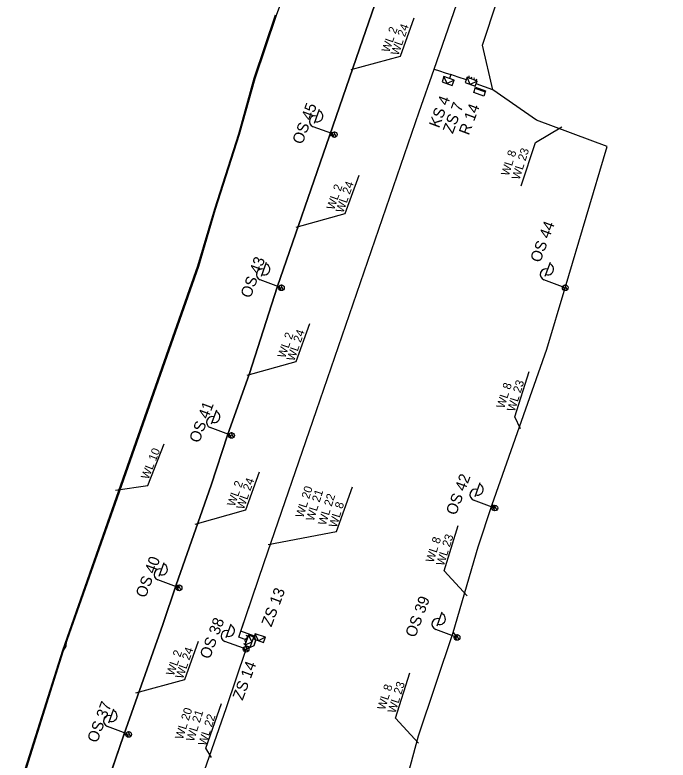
# Model space of a CAD drawing. Extents: x -695448 to -695200, y -1124997 to -1123857.
# Drawn here: x -695394.1 to -695276.7, y -1124378.9 to -1124245 of the extents above; entities that cross this region are included whole.
import ezdxf

# ---------------------------------------------------------------- set-up
doc = ezdxf.new("R2010")
doc.units = 0
doc.layers.add('Vrstva 26', color=7, linetype='Continuous')

msp = doc.modelspace()

# ---------------------------------------------------------------- linework, layer by layer
at = {"layer": 'Vrstva 26'}
for p, q in [((-695311.35, -1124258.15), (-695309.55, -1124258.78)), ((-695340.27, -1124264.4), (-695339.34, -1124261.91)), ((-695337.16, -1124266.31), (-695340.51, -1124265.07)), ((-695336.34, -1124266.88), (-695336.75, -1124265.99)), ((-695337.57, -1124266.71), (-695336.68, -1124266.49)), ((-695336.71, -1124267), (-695337.08, -1124266.18)), ((-695349.79, -1124291.91), (-695348.87, -1124289.42)), ((-695298.75, -1124291.91), (-695297.82, -1124289.42)), ((-695346.68, -1124293.82), (-695350.04, -1124292.58)), ((-695295.64, -1124293.82), (-695299, -1124292.58)), ((-695346.98, -1124293.92), (-695346.2, -1124294)), ((-695346.23, -1124294.51), (-695346.61, -1124293.69)), ((-695345.87, -1124294.38), (-695346.28, -1124293.49)), ((-695295.19, -1124294.51), (-695295.56, -1124293.69)), ((-695294.82, -1124294.38), (-695295.23, -1124293.49)), ((-695358.76, -1124318.44), (-695357.83, -1124315.95)), ((-695355.65, -1124320.36), (-695359, -1124319.12)), ((-695355.89, -1124320.48), (-695355.17, -1124320.54)), ((-695355.2, -1124321.05), (-695355.57, -1124320.23)), ((-695354.83, -1124320.92), (-695355.24, -1124320.03)), ((-695311.39, -1124331.48), (-695310.47, -1124328.99)), ((-695308.29, -1124333.4), (-695311.64, -1124332.16)), ((-695308.31, -1124332.94), (-695307.81, -1124333.57)), ((-695307.84, -1124334.09), (-695308.21, -1124333.27)), ((-695307.47, -1124333.96), (-695307.88, -1124333.07)), ((-695368.2, -1124345.82), (-695367.28, -1124343.33)), ((-695365.09, -1124347.73), (-695368.45, -1124346.49)), ((-695365.14, -1124347.4), (-695364.61, -1124347.91)), ((-695364.64, -1124348.42), (-695365.02, -1124347.6)), ((-695364.28, -1124348.3), (-695364.69, -1124347.41)), ((-695318.21, -1124354.73), (-695317.29, -1124352.23)), ((-695356.14, -1124356.85), (-695355.22, -1124354.36)), ((-695315.1, -1124356.64), (-695318.46, -1124355.4)), ((-695315.29, -1124355.96), (-695314.62, -1124356.82)), ((-695314.65, -1124357.33), (-695315.03, -1124356.51)), ((-695314.29, -1124357.2), (-695314.7, -1124356.31)), ((-695353.03, -1124358.77), (-695356.39, -1124357.53)), ((-695352.58, -1124359.45), (-695352.96, -1124358.64)), ((-695352.22, -1124359.33), (-695352.63, -1124358.44)), ((-695377.25, -1124372.15), (-695376.33, -1124369.66)), ((-695374.15, -1124374.07), (-695377.5, -1124372.82)), ((-695374.55, -1124374.32), (-695373.67, -1124374.24)), ((-695373.7, -1124374.75), (-695374.07, -1124373.94)), ((-695373.33, -1124374.63), (-695373.74, -1124373.74))]:
    msp.add_line(p, q, dxfattribs=at)
for points in [[(-695381.37, -1124394.21), (-695374.55, -1124374.32), (-695367.53, -1124354.51), (-695365.14, -1124347.4), (-695358.86, -1124329.48), (-695355.89, -1124320.48), (-695351.92, -1124309.4), (-695346.98, -1124293.92), (-695337.57, -1124266.71), (-695331.57, -1124249.34), (-695326.77, -1124235.46), (-695320.32, -1124216.82), (-695315.29, -1124202.27), (-695310.65, -1124188.85), (-695308.47, -1124182.54), (-695306.63, -1124177.21), (-695301.3, -1124179.05), (-695292.61, -1124182.99), (-695285.68, -1124185.23), (-695276.67, -1124187.03)], [(-695363.09, -1124389.47), (-695356.09, -1124369.39), (-695352.55, -1124358.94), (-695351.13, -1124358.25), (-695350.83, -1124357.36), (-695351.05, -1124356.58), (-695353.51, -1124355.7), (-695349.28, -1124343.38), (-695339.87, -1124316.03), (-695327.36, -1124279.65), (-695321.42, -1124262.37), (-695318.76, -1124254.71), (-695311.07, -1124232.58), (-695305.06, -1124215.26), (-695300.83, -1124203.07), (-695295.33, -1124186.53), (-695294, -1124182.36), (-695292.61, -1124182.99), (-695290.01, -1124183.83), (-695287.1, -1124184.77), (-695285.68, -1124185.23), (-695276.67, -1124187.03)], [(-695363.09, -1124389.47), (-695356.09, -1124369.39), (-695352.55, -1124358.94), (-695351.13, -1124358.25), (-695350.83, -1124357.36), (-695351.05, -1124356.58), (-695353.51, -1124355.7), (-695349.28, -1124343.38), (-695339.87, -1124316.03), (-695327.36, -1124279.65), (-695321.42, -1124262.37), (-695318.76, -1124254.71), (-695311.07, -1124232.58), (-695305.06, -1124215.26), (-695300.83, -1124203.07), (-695295.33, -1124186.53), (-695294, -1124182.36), (-695292.61, -1124182.99), (-695290.01, -1124183.83), (-695287.1, -1124184.77), (-695285.68, -1124185.23), (-695276.67, -1124187.03)], [(-695351.05, -1124356.58), (-695353.51, -1124355.7), (-695349.28, -1124343.38), (-695339.87, -1124316.03), (-695327.36, -1124279.65), (-695321.42, -1124262.37), (-695318.76, -1124254.71), (-695311.07, -1124232.58), (-695305.06, -1124215.26), (-695300.83, -1124203.07), (-695295.33, -1124186.53), (-695294, -1124182.36), (-695292.61, -1124182.99), (-695285.68, -1124185.23), (-695276.67, -1124187.03)], [(-695295.16, -1124294), (-695287.62, -1124268.59), (-695300.31, -1124263.86), (-695308.19, -1124258.46), (-695310.04, -1124250.44), (-695304.69, -1124234.24), (-695301.63, -1124225), (-695302.1, -1124223.26), (-695302.57, -1124221.53), (-695300.82, -1124216.06), (-695295.91, -1124209.52), (-695289.78, -1124192.6), (-695287.1, -1124184.77), (-695285.68, -1124185.23), (-695276.67, -1124187.03)], [(-695393.96, -1124386.42), (-695385.36, -1124359.17), (-695375.69, -1124331.66), (-695366.33, -1124305.12), (-695361.05, -1124290.12), (-695358.03, -1124279.9), (-695353.72, -1124266.39), (-695350.92, -1124256.38), (-695347.09, -1124245.03), (-695343.69, -1124235.79)], [(-695326.77, -1124235.46), (-695331.57, -1124249.34), (-695337.57, -1124266.71), (-695346.98, -1124293.92), (-695351.92, -1124309.4), (-695355.89, -1124320.48), (-695358.86, -1124329.48), (-695365.14, -1124347.4), (-695367.53, -1124354.51), (-695374.55, -1124374.32), (-695384.22, -1124402.55)], [(-695394.13, -1124386.36), (-695385.53, -1124359.11), (-695375.86, -1124331.6), (-695366.5, -1124305.06), (-695361.22, -1124290.06), (-695358.2, -1124279.84), (-695353.89, -1124266.34), (-695351.1, -1124256.32), (-695347.26, -1124244.97)], [(-695333.66, -1124254.81), (-695324.81, -1124252.36), (-695322.35, -1124245.51)], [(-695352.44, -1124357.31), (-695353.89, -1124356.78), (-695349.28, -1124343.38), (-695339.87, -1124316.03), (-695327.36, -1124279.65), (-695321.42, -1124262.37), (-695318.76, -1124254.71), (-695317.8, -1124255.03), (-695316.76, -1124255.37), (-695315.73, -1124255.7), (-695315.96, -1124256.41)], [(-695315.16, -1124256.69), (-695316.39, -1124257.32), (-695316.97, -1124256.06)], [(-695312.95, -1124256.62), (-695314.4, -1124256.14), (-695315.73, -1124255.7), (-695315.96, -1124256.41)], [(-695311, -1124256.86), (-695312.25, -1124257.46), (-695312.79, -1124256.18)], [(-695325.09, -1124396.92), (-695328.34, -1124395.64), (-695324.84, -1124386.71), (-695321.56, -1124374.49), (-695315.29, -1124355.96), (-695310.83, -1124340.54), (-695308.31, -1124332.94), (-695298.45, -1124305.03), (-695295.16, -1124294), (-695287.62, -1124268.59), (-695300.31, -1124263.86), (-695308.19, -1124258.46), (-695311.18, -1124257.36)], [(-695303.07, -1124275.71), (-695300.53, -1124267.91), (-695295.75, -1124265.11)], [(-695343.57, -1124283.1), (-695334.71, -1124280.64), (-695332.25, -1124273.79)], [(-695324.84, -1124386.71), (-695321.56, -1124374.49), (-695315.29, -1124355.96), (-695310.83, -1124340.54), (-695308.31, -1124332.94), (-695298.45, -1124305.03), (-695295.16, -1124294), (-695295.16, -1124294)], [(-695352.39, -1124309.72), (-695343.53, -1124307.27), (-695341.07, -1124300.42)], [(-695303.22, -1124319.34), (-695304.21, -1124317.17), (-695301.67, -1124309.04)], [(-695376.04, -1124330.36), (-695370.2, -1124329.53), (-695367.3, -1124322.04)], [(-695361.71, -1124336.46), (-695352.59, -1124333.92), (-695350.13, -1124327.07)], [(-695348.59, -1124340.11), (-695336.28, -1124337.78), (-695333.43, -1124329.74)], [(-695312.83, -1124349.36), (-695316.94, -1124344.87), (-695314.4, -1124336.74)], [(-695352.13, -1124356.43), (-695351.51, -1124357.67), (-695352.77, -1124358.24)], [(-695349.1, -1124356.79), (-695350.33, -1124357.41), (-695350.9, -1124356.15)], [(-695390.8, -1124468.79), (-695384.48, -1124451.59), (-695381.11, -1124440.92), (-695375.83, -1124426.72), (-695373.04, -1124418.3), (-695366.56, -1124399.91), (-695363.09, -1124389.47), (-695356.09, -1124369.39), (-695352.55, -1124358.94), (-695351.13, -1124358.25), (-695350.8, -1124357.25)], [(-695372.41, -1124366.8), (-695363.55, -1124364.35), (-695361.09, -1124357.5)], [(-695321.56, -1124375.84), (-695325.67, -1124371.35), (-695323.13, -1124363.21)], [(-695358.79, -1124378.38), (-695359.8, -1124376.74), (-695356.95, -1124368.7)]]:
    msp.add_lwpolyline(points, dxfattribs=at)
for points in [[(-695315.16, -1124256.68), (-695316.97, -1124256.06), (-695317.3, -1124257.01), (-695315.48, -1124257.63)], [(-695311, -1124256.86), (-695312.79, -1124256.18), (-695313.14, -1124257.12), (-695311.35, -1124257.8)], [(-695311.63, -1124258.94), (-695311.3, -1124257.98), (-695309.49, -1124258.61), (-695309.82, -1124259.57)], [(-695352.13, -1124356.43), (-695352.77, -1124358.24), (-695351.83, -1124358.57), (-695351.19, -1124356.76)], [(-695349.09, -1124356.79), (-695350.9, -1124356.15), (-695351.24, -1124357.1), (-695349.43, -1124357.73)], [(-695384.84, -1124357.5), (-695385.29, -1124358.28), (-695385.36, -1124359.17), (-695384.92, -1124358.39)]]:
    msp.add_lwpolyline(points, close=True, dxfattribs=at)
for centre in [(-695336.68, -1124266.49), (-695336.68, -1124266.49), (-695346.2, -1124294), (-695346.2, -1124294), (-695295.16, -1124294), (-695295.16, -1124294), (-695355.17, -1124320.54), (-695355.17, -1124320.54), (-695307.81, -1124333.57), (-695307.81, -1124333.57), (-695364.61, -1124347.91), (-695364.61, -1124347.91), (-695314.62, -1124356.82), (-695314.62, -1124356.82), (-695352.55, -1124358.94), (-695352.55, -1124358.94), (-695373.67, -1124374.24), (-695373.67, -1124374.24)]:
    msp.add_circle(centre, 0.511, dxfattribs=at)
for centre, radius, start, end in [((-695312.24, -1124256.08), 0.285, 147.18, 350.4135), ((-695311.32, -1124256.43), 0.285, 147.18, 350.4135), ((-695340.16, -1124264.11), 1.02, 69.7051, 249.7051), ((-695339.79, -1124263.16), 1.02, 249.0025, 70.4077), ((-695349.32, -1124290.67), 1.02, 249.0025, 70.4077), ((-695298.27, -1124290.67), 1.02, 249.0025, 70.4077), ((-695349.68, -1124291.62), 1.02, 69.7051, 249.7051), ((-695298.64, -1124291.62), 1.02, 69.7051, 249.7051), ((-695358.28, -1124317.2), 1.02, 249.0025, 70.4077), ((-695358.65, -1124318.16), 1.02, 69.7051, 249.7051), ((-695311.29, -1124331.2), 1.02, 69.7051, 249.7051), ((-695310.92, -1124330.24), 1.02, 249.0025, 70.4077), ((-695367.73, -1124344.58), 1.02, 249.0025, 70.4077), ((-695368.09, -1124345.53), 1.02, 69.7051, 249.7051), ((-695317.74, -1124353.48), 1.02, 249.0025, 70.4077), ((-695318.11, -1124354.44), 1.02, 69.7051, 249.7051), ((-695356.03, -1124356.57), 1.02, 69.7051, 249.7051), ((-695355.67, -1124355.61), 1.02, 249.0025, 70.4077), ((-695352.56, -1124356.76), 0.285, 238.3384, 81.5718), ((-695352.89, -1124357.68), 0.285, 238.3384, 81.5718), ((-695376.78, -1124370.91), 1.02, 249.0025, 70.4077), ((-695377.15, -1124371.86), 1.02, 69.7051, 249.7051)]:
    msp.add_arc(centre, radius, start, end, dxfattribs=at)

# ---------------------------------------------------------------- texts
for s, height, rotation, p in [('WL 2', 1.5, 70.5598, (-695326.84, -1124251.84)), ('WL 24', 1.5, 70.5598, (-695325.19, -1124252.39)), ('KS 4', 2, 69.4105, (-695317.86, -1124265.42)), ('ZS 7', 2, 69.4105, (-695315.39, -1124266.44)), ('OS 45', 2, 69.4105, (-695342.45, -1124268.37)), ('R 14', 2, 69.4105, (-695312.5, -1124266.71)), ('WL 8', 1.5, 72.2546, (-695305.34, -1124274.02)), ('WL 23', 1.5, 72.2546, (-695303.41, -1124274.72)), ('WL 2', 1.5, 70.5598, (-695336.75, -1124280.13)), ('WL 24', 1.5, 70.5598, (-695335.1, -1124280.67)), ('OS 44', 2, 69.4105, (-695299.68, -1124289.61)), ('OS 43', 2, 69.4105, (-695351.77, -1124295.99)), ('WL 2', 1.5, 70.5598, (-695345.56, -1124306.75)), ('WL 24', 1.5, 70.5598, (-695343.92, -1124307.3)), ('WL 8', 1.5, 72.2546, (-695306.16, -1124315.8)), ('WL 23', 1.5, 72.2546, (-695304.28, -1124316.39)), ('OS 41', 2, 69.4105, (-695361, -1124322.01)), ('WL 10', 1.5, 68.1219, (-695370.13, -1124328.56)), ('OS 42', 2, 69.4105, (-695314.83, -1124335)), ('WL 2', 1.5, 70.5598, (-695354.63, -1124333.41)), ('WL 24', 1.5, 70.5598, (-695352.98, -1124333.96)), ('WL 20', 1.5, 72.4231, (-695342.3, -1124335.44)), ('WL 21', 1.5, 72.4231, (-695340.42, -1124336.04)), ('WL 22', 1.5, 72.4231, (-695338.25, -1124336.8)), ('WL 8', 1.5, 72.4231, (-695336.31, -1124337.21)), ('WL 23', 1.5, 72.2546, (-695317.01, -1124344.08)), ('WL 8', 1.5, 72.2546, (-695318.89, -1124343.5)), ('OS 40', 2, 69.4105, (-695370.63, -1124349.84)), ('ZS 13', 2, 69.4105, (-695348.01, -1124355.05)), ('OS 39', 2, 69.4105, (-695322.14, -1124356.97)), ('OS 38', 2, 69.4105, (-695359.1, -1124360.84)), ('WL 2', 1.5, 70.5598, (-695365.59, -1124363.83)), ('WL 24', 1.5, 70.5598, (-695363.94, -1124364.38)), ('ZS 14', 2, 69.4105, (-695353.19, -1124368.25)), ('WL 23', 1.5, 72.2546, (-695325.74, -1124370.56)), ('WL 8', 1.5, 72.2546, (-695327.61, -1124369.98)), ('OS 37', 2, 69.4105, (-695379.34, -1124375.89)), ('WL 20', 1.5, 72.4231, (-695363.95, -1124375.27)), ('WL 21', 1.5, 72.4231, (-695361.97, -1124375.65)), ('WL 22', 1.5, 72.4231, (-695359.79, -1124376.41))]:
    msp.add_text(s, height=height, rotation=rotation, dxfattribs=at).set_placement(p)

doc.saveas('drawing.dxf')
